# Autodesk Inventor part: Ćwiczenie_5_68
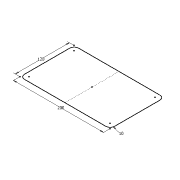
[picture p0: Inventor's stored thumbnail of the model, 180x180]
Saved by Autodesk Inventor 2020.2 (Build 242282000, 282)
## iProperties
Created: 2005-07
Part Number: Ćwiczenie_5_68
Document SubType Name: Modeling
Designer: F.Stasiak
Manufacturer: Standard
Standards Organization: Custom
Material: Aluminium-6061-AHC
Density: 2.71 g/cm^3
Appearance: Cyjan
Manager: www.cadconsulting.pl
Company: Fabian Stasiak CAD Consulting
Author: F.Stasiak
Subject: Zbiór ćwiczeń. Autodesk Inventor 2020. Kurs podstawowy
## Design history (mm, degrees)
sketch "Szkic1"
  geometry: L1 (-90, 60)-(90, 60); L2 (100, 50)-(100, -50); L3 (90, -60)-(-90, -60); L4 (-100, -50)-(-100, 50); L5 (0, 60)-(0, -60); A1 r 10 centre (90, -50) between (90, -60) and (100, -50); A2 r 10 centre (-90, -50) between (-100, -50) and (-90, -60); A3 r 10 centre (-90, 50) between (-90, 60) and (-100, 50); A4 r 10 centre (90, 50) between (100, 50) and (90, 60); 5 further points
  constraints: 10 end point, 8 point on circle, 8 tangent, 6 point on line, 4 centre point, 3 equal radius, 3 midpoint, 2 parallel, 1 coincident, 1 horizontal, 1 perpendicular
  dimensions: "d0" = 200 distance of point (100, -60) point (-100, -60); "d1" = 120 distance of point (-100, -60) point (-100, 60); "d2" = 10 radius of A1
node "Korpusy bryłowe"
node "Korpusy powierzchniowe"
